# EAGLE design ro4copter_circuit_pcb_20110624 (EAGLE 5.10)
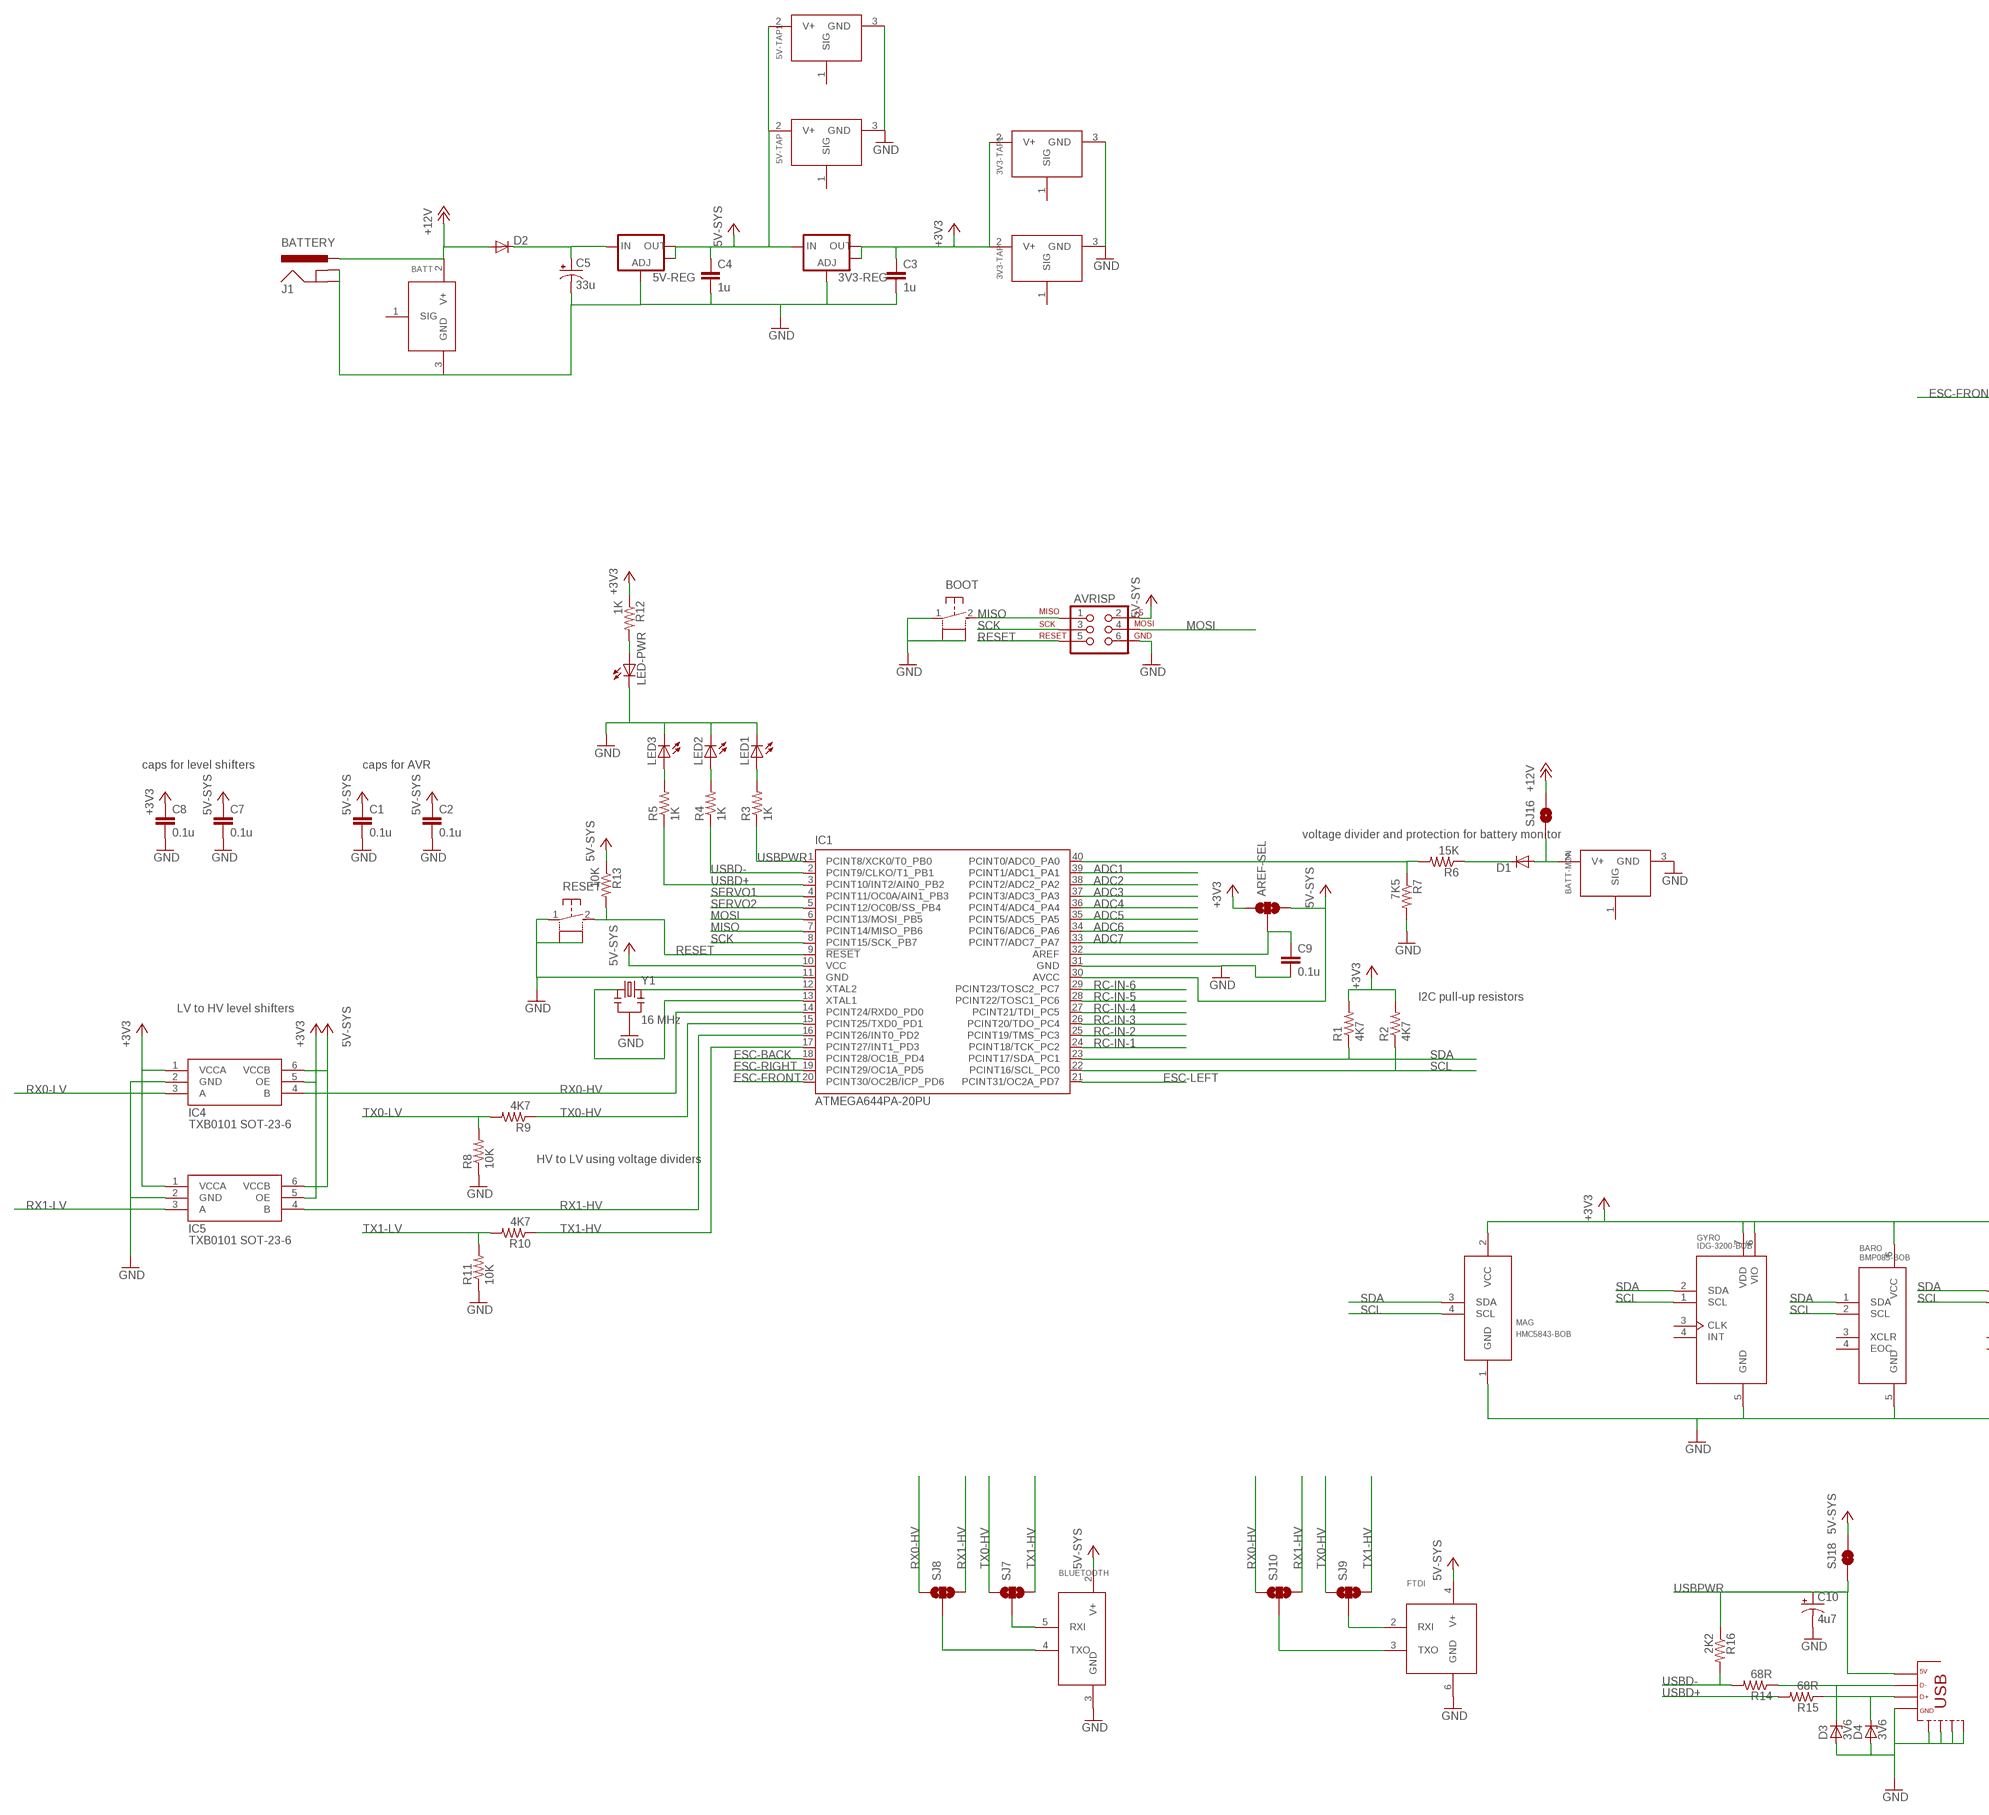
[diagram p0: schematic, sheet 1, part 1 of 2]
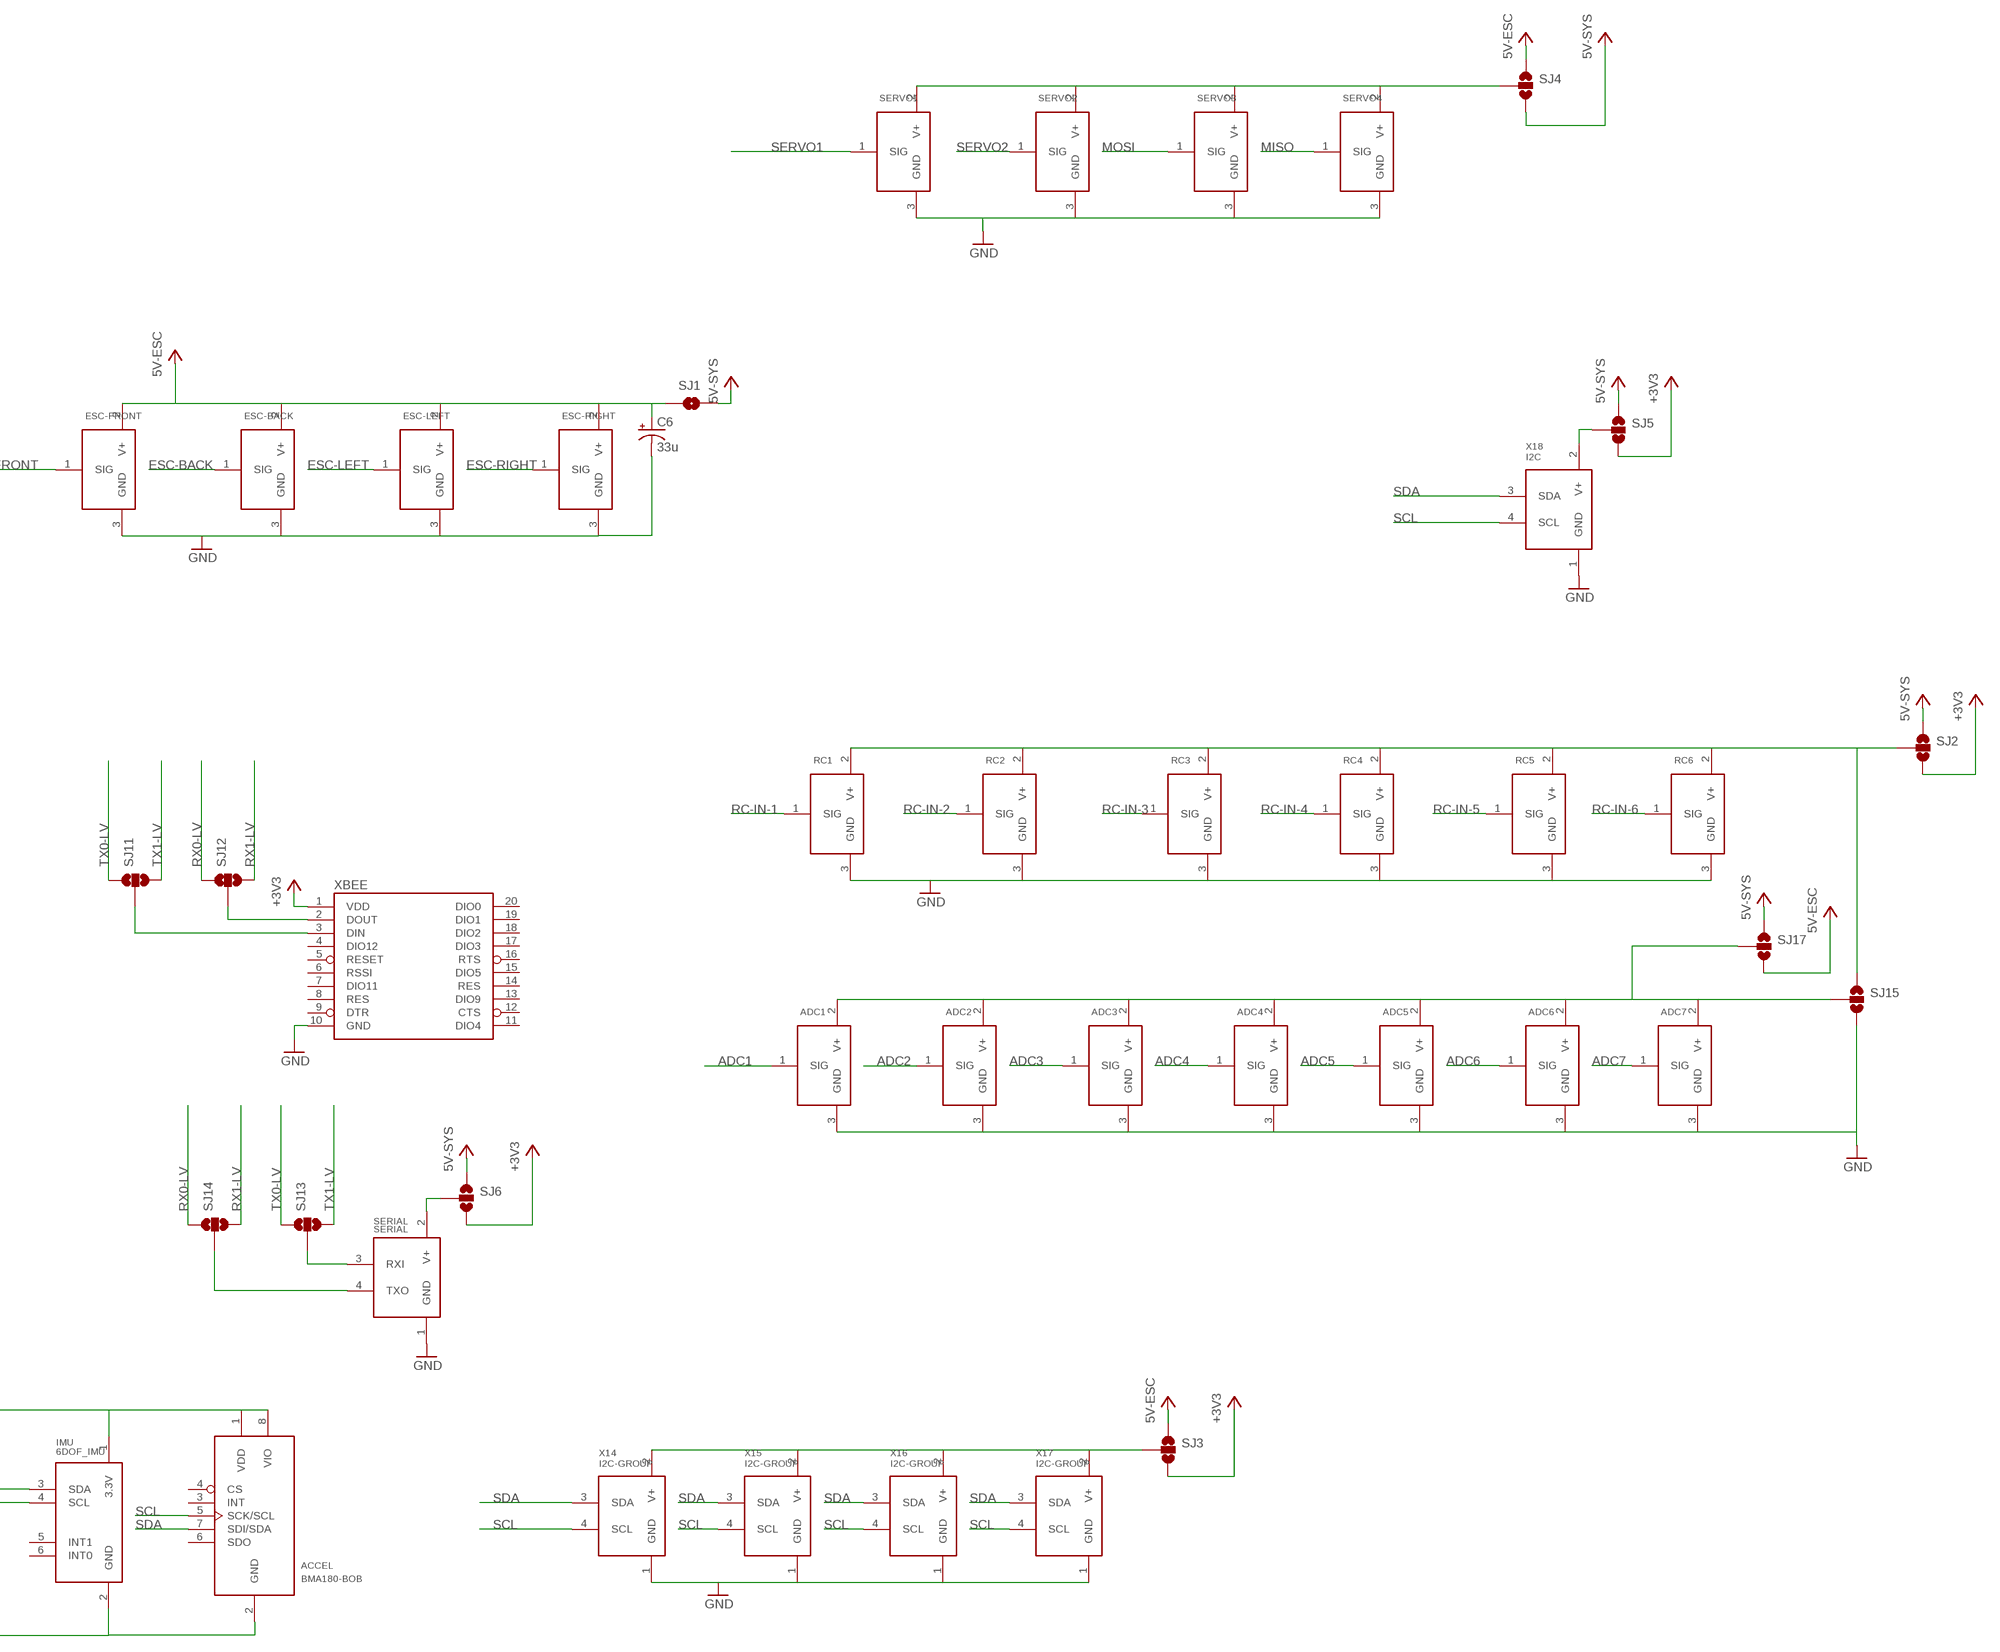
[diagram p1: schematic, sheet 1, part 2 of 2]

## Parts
3V3-REG  V_REG_LM1117SOT223  [SOT223]
3V3-TAP  SERVO-3PINSTANDARD  [SERVO-3PIN]
3V3-TAP1  SERVO-3PINSTANDARD  [SERVO-3PIN]
5V-REG  V_REG_LM1117SOT223  [SOT223]
5V-TAP  SERVO-3PINSTANDARD  [SERVO-3PIN]
5V-TAP1  SERVO-3PINSTANDARD  [SERVO-3PIN]
ACCEL  BMA180-BOB  [BMA180-BOB]
ADC1  SERVO-3PINSTANDARD  [SERVO-3PIN]
ADC2  SERVO-3PINSTANDARD  [SERVO-3PIN]
ADC3  SERVO-3PINSTANDARD  [SERVO-3PIN]
ADC4  SERVO-3PINSTANDARD  [SERVO-3PIN]
ADC5  SERVO-3PINSTANDARD  [SERVO-3PIN]
ADC6  SERVO-3PINSTANDARD  [SERVO-3PIN]
ADC7  SERVO-3PINSTANDARD  [SERVO-3PIN]
AREF-SEL  SOLDERJUMPER_2WAYFERRITE-BEAD  [SJ-FERRITE-BEAD]
AVRISP  AVR_SPI_PRG_6NS  [2X3-NS]
BARO  BMP085-BOB  [BMP085-BOB]
BATT  SERVO-3PINSTANDARD  [SERVO-3PIN]
BATT-MON  SERVO-3PINSTANDARD  [SERVO-3PIN]
BLUETOOTH  BLUESMIRF-CONN  [BLUESMIRF-CONN]
BOOT  SWITCH-TACT-SIDE-31-XX  [B3F-31XX]
C1  0.1u  C-EUC0805  [C0805]
C2  0.1u  C-EUC0805  [C0805]
C3  1u  C-EUC0805  [C0805]
C4  1u  C-EUC0805  [C0805]
C5  33u  CPOL-US153CLV-0505  [153CLV-0505]
C6  33u  CPOL-US153CLV-0505  [153CLV-0505]
C7  0.1u  C-EUC0805  [C0805]
C8  0.1u  C-EUC0805  [C0805]
C9  0.1u  C-EUC0805  [C0805]
C10  4u7  CPOL-USB/3528-21W  [B/3528-21W]
D1  DIODE-MINIMELF  [MINIMELF]
D2  DIODE-SMB  [SMB]
D3  3V6  ZENER-DIODESOD80C  [SOD80C]
D4  3V6  ZENER-DIODESOD80C  [SOD80C]
ESC-BACK  SERVO-3PINSTANDARD  [SERVO-3PIN]
ESC-FRONT  SERVO-3PINSTANDARD  [SERVO-3PIN]
ESC-LEFT  SERVO-3PINSTANDARD  [SERVO-3PIN]
ESC-RIGHT  SERVO-3PINSTANDARD  [SERVO-3PIN]
FTDI  FTDI-CABLE  [FTDI-CABLE-EDGE]
GYRO  IDG-3200-BOB  [ITG-3200-BOB]
IC1  ATMEGA644PA-20PU  ATMEGA644-20PU  [DIL40]
IC4  TXB0101 SOT-23-6  TXB0101SOT-23-6  [SOT-23-6]
IC5  TXB0101 SOT-23-6  TXB0101SOT-23-6  [SOT-23-6]
IMU  6DOF_IMU  [6DOF_IMU]
J1  BATTERY  POWER_JACKPTH  [POWER_JACK_PTH]
LED1  LED3MM  [LED3MM]
LED2  LED3MM  [LED3MM]
LED3  LED3MM  [LED3MM]
LED-PWR  LED3MM  [LED3MM]
MAG  HMC5843-BOB  [HMC5843-BOB]
R1  4K7  R-US_R0805  [R0805]
R2  4K7  R-US_R0805  [R0805]
R3  1K  R-US_R0805  [R0805]
R4  1K  R-US_R0805  [R0805]
R5  1K  R-US_R0805  [R0805]
R6  15K  R-US_R0805  [R0805]
R7  7K5  R-US_R0805  [R0805]
R8  10K  R-US_R0805  [R0805]
R9  4K7  R-US_R0805  [R0805]
R10  4K7  R-US_R0805  [R0805]
R11  10K  R-US_R0805  [R0805]
R12  1K  R-US_R0805  [R0805]
R13  10K  R-US_R0805  [R0805]
R14  68R  R-US_R0805  [R0805]
R15  68R  R-US_R0805  [R0805]
R16  2K2  R-US_R0805  [R0805]
RC1  SERVO-3PINSTANDARD  [SERVO-3PIN]
RC2  SERVO-3PINSTANDARD  [SERVO-3PIN]
RC3  SERVO-3PINSTANDARD  [SERVO-3PIN]
RC4  SERVO-3PINSTANDARD  [SERVO-3PIN]
RC5  SERVO-3PINSTANDARD  [SERVO-3PIN]
RC6  SERVO-3PINSTANDARD  [SERVO-3PIN]
RESET  SWITCH-TACT-SIDE-31-XX  [B3F-31XX]
SERIAL  SERIAL  SERIAL-CONN  [SERIAL-CONN]
SERVO1  SERVO-3PINSTANDARD  [SERVO-3PIN]
SERVO2  SERVO-3PINSTANDARD  [SERVO-3PIN]
SERVO3  SERVO-3PINSTANDARD  [SERVO-3PIN]
SERVO4  SERVO-3PINSTANDARD  [SERVO-3PIN]
SJ1  SOLDERJUMPERNO  [SJ_2S-NO]
SJ2  SOLDERJUMPER_2WAYT  [SJ_2]
SJ3  SOLDERJUMPER_2WAYT  [SJ_2]
SJ4  SOLDERJUMPER_2WAYT  [SJ_2]
SJ5  SOLDERJUMPER_2WAYT  [SJ_2]
SJ6  SOLDERJUMPER_2WAYT  [SJ_2]
SJ7  SOLDERJUMPER_2WAYT  [SJ_2]
SJ8  SOLDERJUMPER_2WAYT  [SJ_2]
SJ9  SOLDERJUMPER_2WAYT  [SJ_2]
SJ10  SOLDERJUMPER_2WAYT  [SJ_2]
SJ11  SOLDERJUMPER_2WAYT  [SJ_2]
SJ12  SOLDERJUMPER_2WAYT  [SJ_2]
SJ13  SOLDERJUMPER_2WAYT  [SJ_2]
SJ14  SOLDERJUMPER_2WAYT  [SJ_2]
SJ15  SOLDERJUMPER_2WAYT  [SJ_2]
SJ16  SOLDERJUMPERNO  [SJ_2S-NO]
SJ17  SOLDERJUMPER_2WAYT  [SJ_2]
SJ18  SOLDERJUMPERNO  [SJ_2S-NO]
U$5  USB-MINIB-WSHIELD  [USB-MINIB]
X14  I2C-GROUP  [I2C-GROUP]
X15  I2C-GROUP  [I2C-GROUP]
X16  I2C-GROUP  [I2C-GROUP]
X17  I2C-GROUP  [I2C-GROUP]
X18  I2C  I2C-GROUP  [I2C-GROUP]
XBEE  XBEE-1XBEE-1_LOCK  [XBEE-1_LOCK]
Y1  16 MHz  RESONATORPTH  [RESONATOR-PTH]

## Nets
5V-ESC: C6.+ ESC-BACK.2(V+) ESC-FRONT.2(V+) ESC-LEFT.2(V+) ESC-RIGHT.2(V+) SJ1.1 SJ3.1 SJ4.1 SJ17.3
+3V3: 3V3-REG.2(OUT) 3V3-REG.4(OUT) 3V3-TAP1.2(V+) 3V3-TAP.2(V+) ACCEL.1(VDD) ACCEL.8(VIO) AREF-SEL.1 BARO.6(VCC) C3.1 C8.1 GYRO.6(VIO) GYRO.7(VDD) IC4.1(VCCA) IC4.5(OE) IC5.1(VCCA) IC5.5(OE) IMU.1(3.3V) MAG.2(VCC) R1.2 R2.2 R12.1 SJ2.3 SJ3.3 SJ5.3 SJ6.3 XBEE.1(VDD)
+5V: 3V3-REG.3(IN) 5V-REG.2(OUT) 5V-REG.4(OUT) 5V-TAP1.2(V+) 5V-TAP.2(V+) AREF-SEL.3 AVRISP.2 BLUETOOTH.2(V+) C1.1 C2.1 C4.1 C7.1 FTDI.4(V+) IC1.10(VCC) IC1.30(AVCC) IC4.6(VCCB) IC5.6(VCCB) R13.1 SJ1.2 SJ2.1 SJ4.3 SJ5.1 SJ6.1 SJ17.1 SJ18.2 ; supply symbol labelled 5V-SYS
+12V: BATT.2(V+) D2.A J1.PWR SJ16.2
ADC1: ADC1.1(SIG) IC1.39(PCINT1/ADC1_PA1)
ADC2: ADC2.1(SIG) IC1.38(PCINT2/ADC2_PA2)
ADC3: ADC3.1(SIG) IC1.37(PCINT3/ADC3_PA3)
ADC4: ADC4.1(SIG) IC1.36(PCINT4/ADC4_PA4)
ADC5: ADC5.1(SIG) IC1.35(PCINT5/ADC5_PA5)
ADC6: ADC6.1(SIG) IC1.34(PCINT6/ADC6_PA6)
ADC7: ADC7.1(SIG) IC1.33(PCINT7/ADC7_PA7)
ESC-BACK: ESC-BACK.1(SIG) IC1.18(PCINT28/OC1B_PD4)
ESC-FRONT: ESC-FRONT.1(SIG) IC1.20(PCINT30/OC2B/ICP_PD6)
ESC-LEFT: ESC-LEFT.1(SIG) IC1.21(PCINT31/OC2A_PD7)
ESC-RIGHT: ESC-RIGHT.1(SIG) IC1.19(PCINT29/OC1A_PD5)
GND: 3V3-REG.1(ADJ) 3V3-TAP1.3(GND) 3V3-TAP.3(GND) 5V-REG.1(ADJ) 5V-TAP1.3(GND) 5V-TAP.3(GND) ACCEL.2(GND) ADC1.3(GND) ADC2.3(GND) ADC3.3(GND) ADC4.3(GND) ADC5.3(GND) ADC6.3(GND) ADC7.3(GND) AVRISP.6 BARO.5(GND) BATT-MON.3(GND) BATT.3(GND) BLUETOOTH.3(GND) BOOT.1(P) BOOT.S@3(S) BOOT.S@4(S) C1.2 C2.2 C3.2 C4.2 C5.- C6.- C7.2 C8.2 C9.2 C10.- D3.A D4.A ESC-BACK.3(GND) ESC-FRONT.3(GND) ESC-LEFT.3(GND) ESC-RIGHT.3(GND) FTDI.6(GND) GYRO.5(GND) IC1.11(GND) IC1.31(GND) IC4.2(GND) IC5.2(GND) IMU.2(GND) J1.GND J1.GNDBREAK LED1.K(C) LED2.K(C) LED3.K(C) LED-PWR.K(C) MAG.1(GND) R7.2 R8.1 R11.1 RC1.3(GND) RC2.3(GND) RC3.3(GND) RC4.3(GND) RC5.3(GND) RC6.3(GND) RESET.1(P) RESET.S@3(S) RESET.S@4(S) SERIAL.1(GND) SERVO1.3(GND) SERVO2.3(GND) SERVO3.3(GND) SERVO4.3(GND) SJ15.3 U$5.GND U$5.GND@1(SHIELD) U$5.GND@2(SHIELD) U$5.GND@3(SHIELD) U$5.GND@4(SHIELD) X14.1(GND) X15.1(GND) X16.1(GND) X17.1(GND) X18.1(GND) XBEE.10(GND) Y1.2
MISO: AVRISP.1 BOOT.2(S) IC1.7(PCINT14/MISO_PB6) SERVO4.1(SIG)
MOSI: AVRISP.4 IC1.6(PCINT13/MOSI_PB5) SERVO3.1(SIG)
N$1: IC1.12(XTAL2) Y1.3
N$2: IC1.13(XTAL1) Y1.1
N$3: LED3.A R5.2
N$4: LED2.A R4.2
N$5: LED1.A R3.2
N$6: SJ3.2 X14.2(V+) X15.2(V+) X16.2(V+) X17.2(V+)
N$8: RC1.2(V+) RC2.2(V+) RC3.2(V+) RC4.2(V+) RC5.2(V+) RC6.2(V+) SJ2.2 SJ15.1
N$11: IC1.40(PCINT0/ADC0_PA0) R6.2 R7.1
N$12: SJ5.2 X18.2(V+)
N$13: D1.C R6.1
N$14: BATT-MON.2(V+) D1.A SJ16.1
N$15: SERIAL.2(V+) SJ6.2
N$16: 5V-REG.3(IN) C5.+ D2.C
N$17: BLUETOOTH.5(RXI) SJ7.2
N$18: BLUETOOTH.4(TXO) SJ8.2
N$19: FTDI.2(RXI) SJ9.2
N$20: SERVO1.2(V+) SERVO2.2(V+) SERVO3.2(V+) SERVO4.2(V+) SJ4.2
N$21: FTDI.3(TXO) SJ10.2
N$22: SJ12.2 XBEE.2(DOUT)
N$23: SJ11.2 XBEE.3(DIN)
N$24: LED-PWR.A R12.2
N$25: AREF-SEL.2 C9.1 IC1.32(AREF)
N$31: SERIAL.3(RXI) SJ13.2
N$32: SERIAL.4(TXO) SJ14.2
N$34: ADC1.2(V+) ADC2.2(V+) ADC3.2(V+) ADC4.2(V+) ADC5.2(V+) ADC6.2(V+) ADC7.2(V+) SJ15.2 SJ17.2
N$42: D3.C R14.1 U$5.D-
N$43: D4.C R15.1 U$5.D+
RC-IN-1: IC1.24(PCINT18/TCK_PC2) RC1.1(SIG)
RC-IN-2: IC1.25(PCINT19/TMS_PC3) RC2.1(SIG)
RC-IN-3: IC1.26(PCINT20/TDO_PC4) RC3.1(SIG)
RC-IN-4: IC1.27(PCINT21/TDI_PC5) RC4.1(SIG)
RC-IN-5: IC1.28(PCINT22/TOSC1_PC6) RC5.1(SIG)
RC-IN-6: IC1.29(PCINT23/TOSC2_PC7) RC6.1(SIG)
RESET: AVRISP.5 IC1.9(!RESET) R13.2 RESET.2(S)
RX0-HV: IC1.14(PCINT24/RXD0_PD0) IC4.4(B) SJ8.1 SJ10.1
RX0-LV: IC4.3(A) SJ12.1 SJ14.1
RX1-HV: IC1.16(PCINT26/INT0_PD2) IC5.4(B) SJ8.3 SJ10.3
RX1-LV: IC5.3(A) SJ12.3 SJ14.3
SCK: AVRISP.3 IC1.8(PCINT15/SCK_PB7)
SCL: ACCEL.5(SCK/SCL) BARO.2(SCL) GYRO.1(SCL) IC1.22(PCINT16/SCL_PC0) IMU.4(SCL) MAG.4(SCL) R2.1 X14.4(SCL) X15.4(SCL) X16.4(SCL) X17.4(SCL) X18.4(SCL)
SDA: ACCEL.7(SDI/SDA) BARO.1(SDA) GYRO.2(SDA) IC1.23(PCINT17/SDA_PC1) IMU.3(SDA) MAG.3(SDA) R1.1 X14.3(SDA) X15.3(SDA) X16.3(SDA) X17.3(SDA) X18.3(SDA)
SERVO1: IC1.4(PCINT11/OC0A/AIN1_PB3) SERVO1.1(SIG)
SERVO2: IC1.5(PCINT12/OC0B/SS_PB4) SERVO2.1(SIG)
TX0-HV: IC1.15(PCINT25/TXD0_PD1) R9.1 SJ7.1 SJ9.1
TX0-LV: R8.2 R9.2 SJ11.1 SJ13.1
TX1-HV: IC1.17(PCINT27/INT1_PD3) R10.1 SJ7.3 SJ9.3
TX1-LV: R10.2 R11.2 SJ11.3 SJ13.3
USBD+: IC1.3(PCINT10/INT2/AIN0_PB2) R5.1 R15.2
USBD-: IC1.2(PCINT9/CLKO/T1_PB1) R4.1 R14.2 R16.2
USBPWR: C10.+ IC1.1(PCINT8/XCK0/T0_PB0) R3.1 R16.1 SJ18.1 U$5.VBUS(V+)
Unconnected: 3V3-TAP1.1(SIG) 3V3-TAP.1(SIG) 5V-TAP1.1(SIG) 5V-TAP.1(SIG) ACCEL.3(INT) ACCEL.4(CS) ACCEL.6(SDO) BARO.3(XCLR) BARO.4(EOC) BATT-MON.1(SIG) BATT.1(SIG) GYRO.3(CLK) GYRO.4(INT) IMU.5(INT1) IMU.6(INT0) XBEE.4(DIO12) XBEE.5(RESET) XBEE.6(RSSI) XBEE.7(DIO11) XBEE.8(RES) XBEE.9(DTR) XBEE.11(DIO4) XBEE.12(CTS) XBEE.13(DIO9) XBEE.14(RES) XBEE.15(DIO5) XBEE.16(RTS) XBEE.17(DIO3) XBEE.18(DIO2) XBEE.19(DIO1) XBEE.20(DIO0)

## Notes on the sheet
- caps for level shifters | caps for AVR
- voltage divider and protection for battery monitor
- I2C pull-up resistors
- LV to HV level shifters
- HV to LV using voltage dividers

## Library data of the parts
3V3-REG 5V-REG = aq_pcb_v2:V_REG_LM1117: Voltage Regulator LM1117 Standard adjustable voltage regulator but in SMD form. Spark Fun Electronics SKU : COM-00595
3V3-TAP 3V3-TAP1 5V-TAP 5V-TAP1 ADC1-ADC7 BATT BATT-MON ESC-BACK ESC-FRONT ESC-LEFT ESC-RIGHT RC1-RC6 SERVO1-SERVO4 = aq_pcb_v2:SERVO-3PIN
ACCEL = aq_pcb_v2:BMA180-BOB
AREF-SEL SJ2-SJ15 SJ17 = aq_pcb_v2:SOLDERJUMPER_2WAY: Solder Jumper 2 way solder jumper
AVRISP = aq_pcb_v2:AVR_SPI_PRG_6: AVR ISP 6 Pin This is the reduced ISP connector for AVR programming. Common on Arduino. This footprint will take up less PCB space and can be used with a 10-pin to 6-pin adapter such as SKU: BOB-08508
BARO = aq_pcb_v2:BMP085-BOB
BLUETOOTH = aq_pcb_v2:BLUESMIRF-CONN
BOOT RESET = aq_pcb_v2:SWITCH-TACT-SIDE-31-XX: OMRON SWITCH
C1-C4 C7-C9 = rcl:C-EU: CAPACITOR, European symbol
C5 C6 C10 = rcl:CPOL-US: POLARIZED CAPACITOR, American symbol
D1 D2 = diode:DIODE-: DIODE
D3 D4 = diode:ZENER-DIODE: Z-Diode
FTDI = aq_pcb_v2:FTDI-CABLE
GYRO = aq_pcb_v2:IDG-3200-BOB
IC1 = aq_pcb_v2:ATMEGA644-*PU: 8-bit Microcontroller with 64K Bytes In-System Programmable Flash Auto generated by make-symbol-device-package-bsdl.ulp Rev. 34 Source: http://www.atmel.com/dyn/resources/prod_documents/doc2593.pdf
IC4 IC5 = aq_pcb_v2:TXB0101
IMU = aq_pcb_v2:6DOF_IMU
J1 = aq_pcb_v2:POWER_JACK: Power Jack This is the standard 5.5mm barrel jack for power. The PTH is the most common, proven, reliable, footprint. All others are experimental. The Slot footprint only works if the mill layer is transmitted to the PCB fab house so be warned. Spark Fun Electronics SKU : PRT-00119. Mating wall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
LED1-LED3 LED-PWR = aq_pcb_v2:LED: LEDs
MAG = aq_pcb_v2:HMC5843-BOB
R1-R16 = rcl:R-US_: RESISTOR, American symbol
SERIAL = aq_pcb_v2:SERIAL-CONN
SJ1 SJ16 SJ18 = aq_pcb_v2:SOLDERJUMPER: Solder Jumper
U$5 = aq_pcb_v2:USB-MINIB-WSHIELD
X14-X18 = aq_pcb_v2:I2C-GROUP
XBEE = aq_pcb_v2:XBEE-1
Y1 = aq_pcb_v2:RESONATOR: Resonator Small SMD resonator. This is the itty bitty 10/20MHz resonators with built in caps. CSTCE10M0G55 and CSTCE20M0V53. Footprint has been reviewed closely but hasn't been tested yet.

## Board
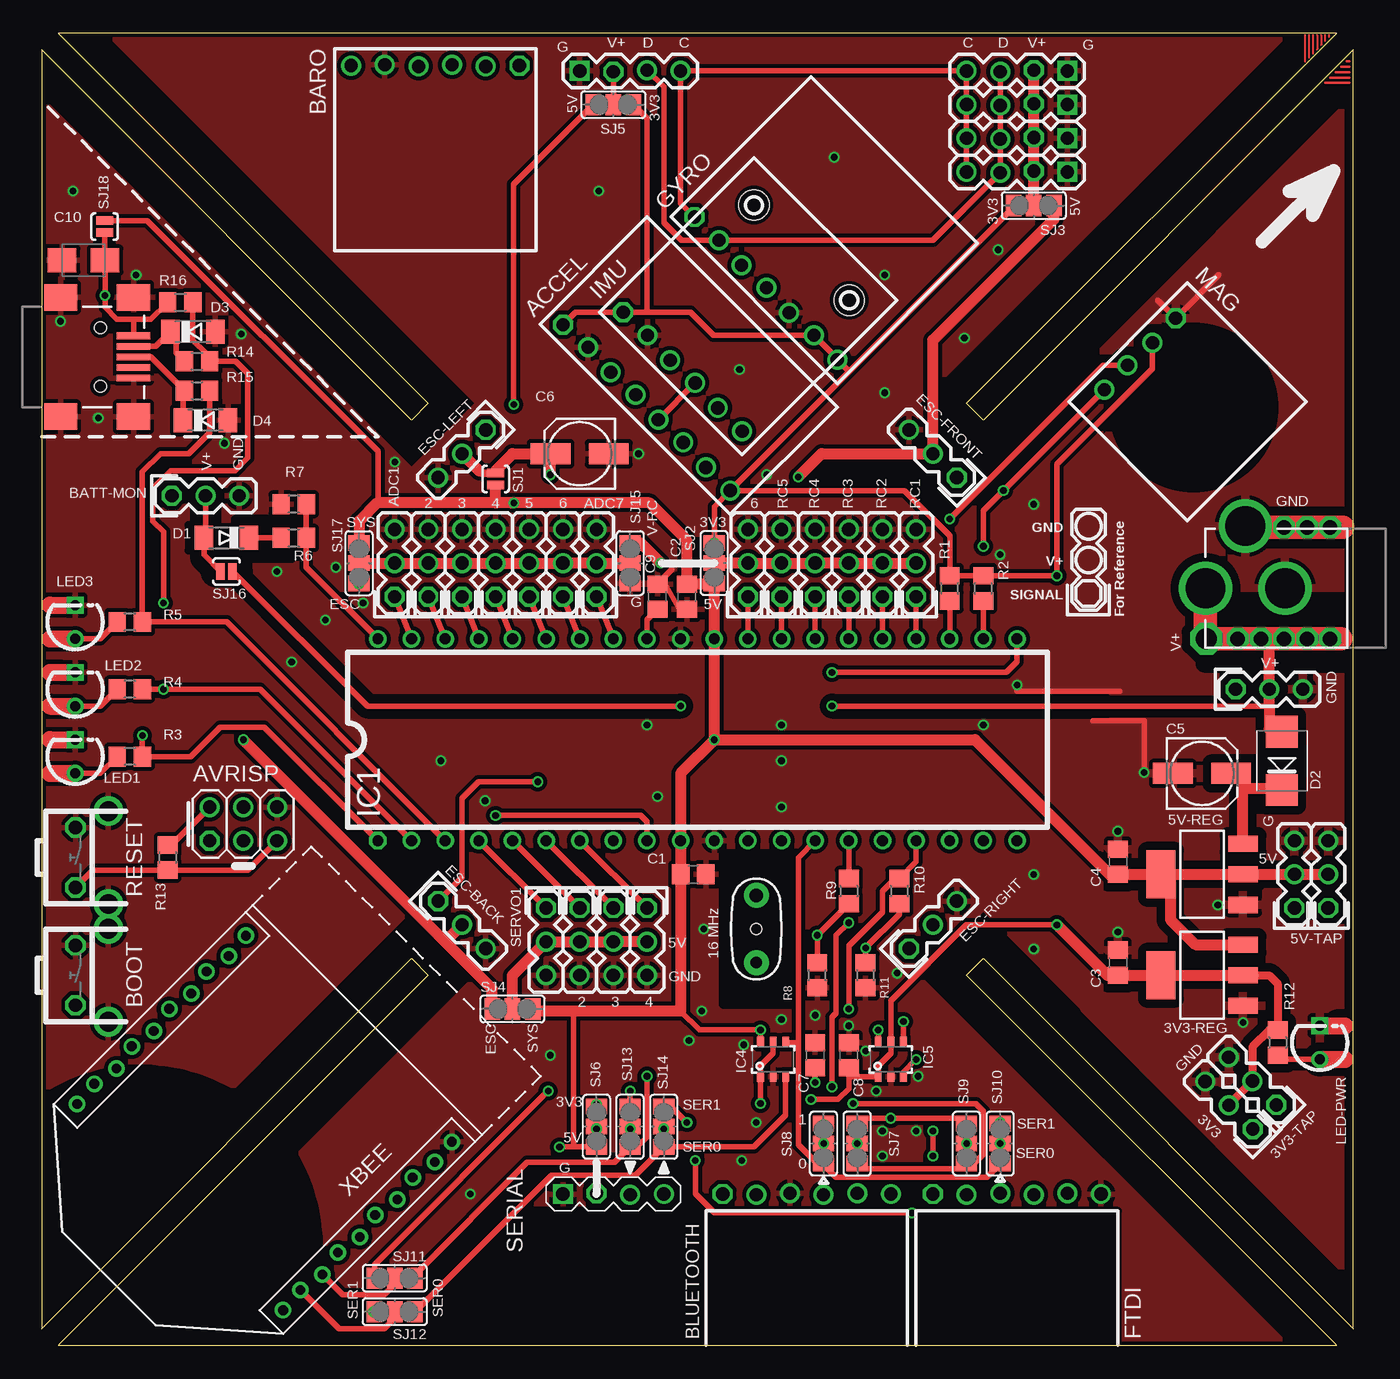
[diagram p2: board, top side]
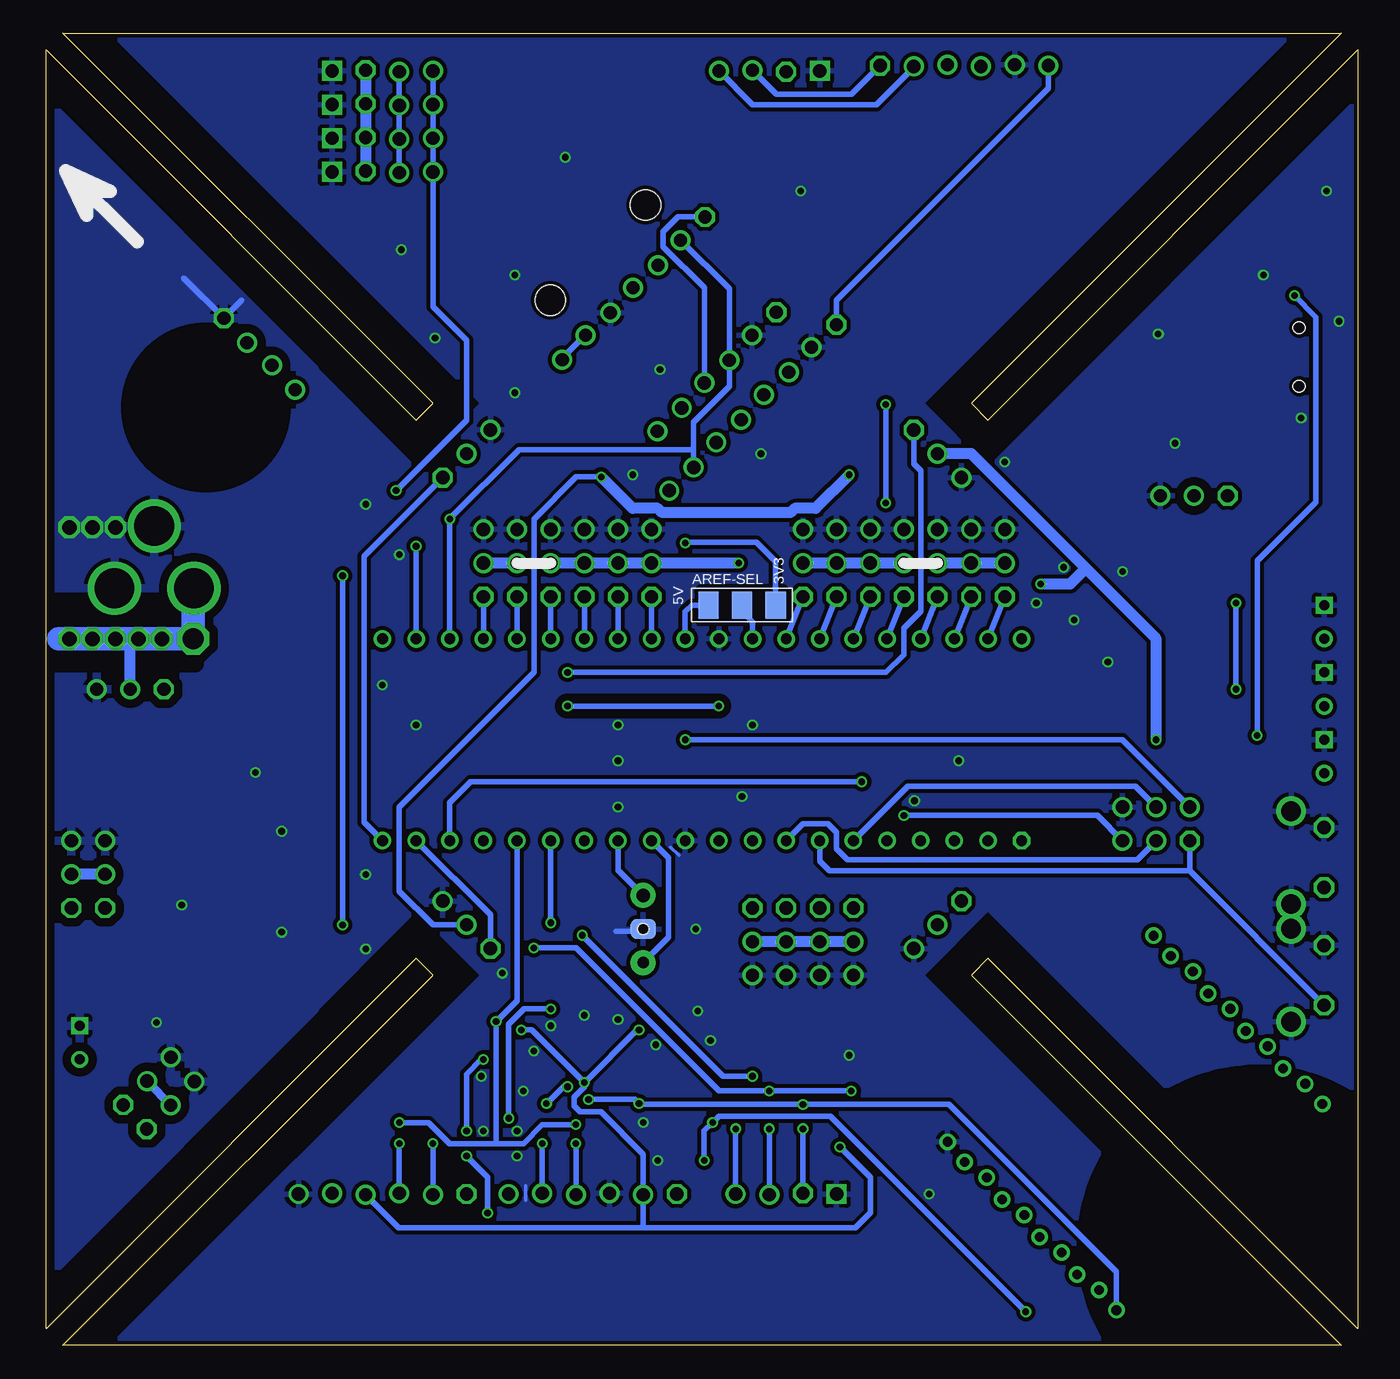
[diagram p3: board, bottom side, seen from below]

Size 99.06 x 99.06 mm. Coordinates in mm from the lower left corner, seen from the top.
Outline: 27.94,29.21 29.21,27.94 1.27,0 97.79,0 69.85,27.94 71.12,29.21 99.06,1.27 99.06,97.79 71.12,69.85 69.85,71.12 97.79,99.06 1.27,99.06 29.21,71.12 27.94,69.85 0,97.79 0,1.27 27.94,29.21
Copper layers (1*16): Top 0.035mm / dielectric 1.5mm / Bottom 0.035mm
Design rules "Fusion_eagle_rule_v1.1_TentedVias2 *": minimum track width 6mil, minimum drill 0.5mm, track to track 6mil, track to pad 6mil, pad to pad 6mil, via to via 6mil, smd to smd 0mil, copper to edge 10mil, drill to drill 10mil, minimum pad ring 10mil, minimum via ring 6mil, stop-mask expansion 2mil, vias tented up to drill 25mil, thermal gap 12mil
tKeepout: area 36.8,0 to 49.5,10.2
tRestrict: area 36.8,0 to 49.5,10.2; area 92.4,43.2 to 94.9,45.1; area 13,60.2 to 14.9,61.8; area 87.8,51.4 to 99.1,56.2; area 12.2,63.9 to 12.6,64.4; area 14.6,59.4 to 18.9,62.4; area 11.1,60 to 11.7,61.9; 13 lines
bRestrict: area 87.8,51.4 to 99.1,56.2; area 12.2,63.9 to 12.6,64.4; 1 lines

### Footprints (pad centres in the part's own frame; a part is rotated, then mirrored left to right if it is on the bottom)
SOT223 = smd 1.219 x 2.235: 1 -2.311,-3.099; 2 0,-3.099; 3 2.311,-3.099 | smd 3.6 x 2.2: 4 0,3.099
SERVO-3PIN = drill 1 octagon: 1 0,-2.54 | drill 1 round: 2 0,0; 3 0,2.54
BMA180-BOB = drill 1 octagon: 1 -8.89,-0.064 | drill 1 round: 2 -6.35,0.064; 3 -3.81,-0.064; 4 -1.27,0.064; 5 1.27,-0.064; 6 3.81,0.064; 7 6.35,-0.064; 8 8.89,0
SJ-FERRITE-BEAD = smd 1.524 x 2.032: 1 -2.54,0; 2 0,0; 3 2.54,0
2X3-NS = drill 1 octagon: 1 -2.54,-1.27 | drill 1 round: 2 -2.54,1.27; 3 0,-1.27; 4 0,1.27; 5 2.54,-1.27; 6 2.54,1.27
BMP085-BOB = drill 1 octagon: 1 -6.35,0 | drill 1 round: 2 -3.81,0.064; 3 -1.27,-0.064; 4 1.27,0.064; 5 3.81,-0.064; 6 6.35,0
BLUESMIRF-CONN = drill 1 octagon: 1 -6.35,0 | drill 1 round: 2 -3.81,-0.064; 3 -1.27,0.064; 4 1.27,-0.064; 5 3.81,0.064; 6 6.35,0
B3F-31XX = drill 1.016 octagon: 1 -2.261,-1.245; 2 2.261,-1.245 | drill 1.499 pad 2.159 round: S@3 -3.505,1.245; S@4 3.505,1.245
C0805 = smd 1.3 x 1.5: 1 -0.95,0; 2 0.95,0
153CLV-0505 = smd 3 x 1.6: + 2.2,0; - -2.2,0
B/3528-21W = smd 2.15 x 1.8: + 1.625,0; - -1.625,0
MINIMELF = smd 1.4 x 1.8: A 1.7,0; C -1.7,0
SMB = smd 2.4 x 2.4: A 2.2,0; C -2.2,0
SOD80C = smd 1.4 x 1.8: A 1.7,0; C -1.7,0
FTDI-CABLE-EDGE = drill 1 octagon: 1 -6.35,0 | drill 1 round: 2 -3.81,-0.064; 3 -1.27,0.064; 4 1.27,-0.064; 5 3.81,0.064; 6 6.35,0
ITG-3200-BOB = drill 1 octagon: 1 -7.62,0 | drill 1 round: 2 -5.08,0.064; 3 -2.54,-0.064; 4 0,0.064; 5 2.54,-0.064; 6 5.08,0.064; 7 7.62,0
DIL40 = drill 0.813 octagon: 1 -24.13,-7.62 | drill 0.813 round: 2 -21.59,-7.62; 3 -19.05,-7.62; 4 -16.51,-7.62; 5 -13.97,-7.62; 6 -11.43,-7.62; 7 -8.89,-7.62; 8 -6.35,-7.62; 9 -3.81,-7.62; 10 -1.27,-7.62; 11 1.27,-7.62; 12 3.81,-7.62; 13 6.35,-7.62; 14 8.89,-7.62; 15 11.43,-7.62; 16 13.97,-7.62; 17 16.51,-7.62; 18 19.05,-7.62; 19 21.59,-7.62; 20 24.13,-7.62; 21 24.13,7.62; 22 21.59,7.62; 23 19.05,7.62; 24 16.51,7.62; 25 13.97,7.62; 26 11.43,7.62; 27 8.89,7.62; 28 6.35,7.62; 29 3.81,7.62; 30 1.27,7.62; 31 -1.27,7.62; 32 -3.81,7.62; 33 -6.35,7.62; 34 -8.89,7.62; 35 -11.43,7.62; 36 -13.97,7.62; 37 -16.51,7.62; 38 -19.05,7.62; 39 -21.59,7.62; 40 -24.13,7.62
SOT-23-6 = smd 0.51 x 0.8: 1 -0.95,-1.3; 2 0,-1.3; 3 0.95,-1.3; 4 0.95,1.3; 5 0,1.3; 6 -0.95,1.3
6DOF_IMU = drill 1 octagon: 1 0,-6.35 | drill 1 round: 2 -0.064,-3.81; 3 0.064,-1.27; 4 -0.064,1.27; 5 0.064,3.81; 6 0,6.35 | hole 2.286: -12.7,5.08; -12.7,-5.08
POWER_JACK_PTH = drill 2.997 round: GND 0,7.7; GNDBREAK 4.7,10.7; PWR 0,13.7
LED3MM = drill 0.762 pad 1.27 round: A -1.27,0 | drill 0.762 pad 1.27 square: K 1.27,0
HMC5843-BOB = drill 1 octagon: 1 -3.81,0 | drill 1 round: 2 -1.27,0.064; 3 1.27,-0.064; 4 3.81,0
R0805 = smd 1.3 x 1.5: 1 -0.95,0; 2 0.95,0
SERIAL-CONN = drill 1 square: 1 -3.81,0 | drill 1 octagon: 2 -1.27,0.064 | drill 1 round: 3 1.27,-0.064; 4 3.81,0
SJ_2S-NO = smd 0.635 x 1.27: 1 -0.45,0; 2 0.45,0
SJ_2 = smd 1.168 x 1.6: 1 -1.524,0; 2 0,0; 3 1.524,0
USB-MINIB = smd 2.5 x 0.5: D+ 2.5,0; D- 2.5,0.8; GND 2.5,-1.6; ID 2.5,-0.8; VBUS 2.5,1.6 | smd 2.5 x 2: GND@1 -3,-4.5; GND@2 -3,4.5; GND@3 2.5,4.5; GND@4 2.5,-4.5 | hole 0.9: 0,2.2; 0,-2.2
I2C-GROUP = drill 1 square: 1 -3.81,0 | drill 1 octagon: 2 -1.27,-0.064 | drill 1 round: 3 1.27,0.064; 4 3.81,0
XBEE-1_LOCK = drill 0.737 round: 1 -10.987,20; 2 -10.822,18; 3 -11.178,16; 4 -10.822,14; 5 -11.178,12; 6 -10.822,10; 7 -11.178,8; 8 -10.822,6; 9 -11.178,4; 10 -11.013,2; 11 10.987,2; 12 10.822,4; 13 11.178,6; 14 10.822,8; 15 11.178,10; 16 10.822,12; 17 11.178,14; 18 10.822,16; 19 11.178,18; 20 11.013,20
RESONATOR-PTH = drill 1.016 pad 1.88 round: 1 -2.54,0 | smd 1.524 x 1.905 bottom: 2 0,0 | drill 0.864 pad 1.88 round: 3 2.54,0 | hole 0.825: 0,0

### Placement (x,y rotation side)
3V3-REG  87.63,27.94 90 top
3V3-TAP  91.44,19.95 45 top
3V3-TAP1  89.66,18.13 45 top
5V-REG  87.63,35.56 90 top
5V-TAP  94.61,35.56 0 top
5V-TAP1  97.16,35.56 0 top
ACCEL  45.72,70.81 315 top
ADC1  26.67,59.05 0 top
ADC2  29.21,59.05 0 top
ADC3  31.75,59.05 0 top
ADC4  34.29,59.05 0 top
ADC5  36.83,59.05 0 top
ADC6  39.37,59.05 0 top
ADC7  41.91,59.05 0 top
AREF-SEL  46.51,55.88 180 bottom
AVRISP  15.24,39.37 0 top
BARO  29.74,96.61 180 top
BATT  92.71,49.53 270 top
BATT-MON  12.38,64.14 270 top
BLUETOOTH  57.78,11.43 0 top
BOOT  3.81,27.94 270 top
C1  49.21,35.56 0 top
C2  48.74,56.52 270 top
C3  81.28,28.89 90 top
C4  81.28,36.51 90 top
C5  87.63,43.18 0 top
C6  40.64,67.31 180 top
C7  58.42,21.91 90 top
C8  60.96,21.91 90 top
C9  46.51,56.52 90 top
C10  3.17,81.92 0 top
D1  13.97,60.96 180 top
D2  93.66,44.13 90 top
D3  11.43,76.52 0 top
D4  12.38,69.85 0 top
ESC-BACK  31.75,31.75 225 top
ESC-FRONT  67.31,67.31 45 top
ESC-LEFT  31.75,67.31 135 top
ESC-RIGHT  67.31,31.75 315 top
FTDI  73.66,11.43 0 top
GYRO  54.7,79.79 315 top
IC1  49.53,45.72 0 top
IC4  55.24,21.59 0 top
IC5  64.14,21.59 0 top
IMU  48.41,73.51 225 top
J1  101.6,57.15 90 top
LED1  2.54,44.45 90 top
LED2  2.54,49.53 90 top
LED3  2.54,54.61 90 top
LED-PWR  96.52,22.86 90 top
MAG  82.95,74.84 225 top
R1  68.58,57.15 90 top
R2  71.12,57.15 90 top
R3  6.67,44.45 180 top
R4  6.67,49.53 180 top
R5  6.67,54.61 180 top
R6  19.05,60.96 0 top
R7  19.05,63.5 180 top
R8  58.58,27.94 90 top
R9  60.96,34.29 270 top
R10  64.77,34.29 270 top
R11  62.23,27.94 90 top
R12  93.34,22.86 270 top
R13  9.53,36.83 270 top
R14  11.75,74.3 0 top
R15  11.75,72.07 0 top
R16  10.48,78.74 0 top
RC1  66.04,59.05 0 top
RC2  63.5,59.05 0 top
RC3  60.96,59.05 0 top
RC4  58.42,59.05 0 top
RC5  55.88,59.05 0 top
RC6  53.34,59.05 0 top
RESET  3.81,36.83 270 top
SERIAL  43.18,11.43 0 top
SERVO1  38.1,30.48 180 top
SERVO2  40.64,30.48 180 top
SERVO3  43.18,30.48 180 top
SERVO4  45.72,30.48 180 top
SJ1  34.29,65.41 270 top
SJ2  50.8,59.05 90 top
SJ3  74.93,86.04 180 top
SJ4  35.56,25.4 0 top
SJ5  43.18,93.66 0 top
SJ6  41.91,16.51 90 top
SJ7  61.59,15.24 90 top
SJ8  59.05,15.24 90 top
SJ9  69.85,15.24 90 top
SJ10  72.39,15.24 90 top
SJ11  26.67,5.08 180 top
SJ12  26.67,2.54 180 top
SJ13  44.45,16.51 90 top
SJ14  46.99,16.51 90 top
SJ15  44.45,59.05 270 top
SJ16  13.97,58.42 0 top
SJ17  23.97,59.05 270 top
SJ18  4.76,84.45 90 top
U$2  [SERVO-3PIN-REFERENCE]  79.06,59.29 90 top
U$3  [ARROR-DIR-REFERENCE]  93.98,85.09 315 top
U$4  [ARROR-DIR-REFERENCE]  93.98,85.09 45 bottom
U$5  4.45,74.61 0 top
X14  73.66,96.2 180 top
X15  73.66,93.66 180 top
X16  73.66,91.12 180 top
X17  73.66,88.58 180 top
X18  44.45,96.2 0 top
XBEE  24.62,24.57 135 top
Y1  53.98,31.43 270 top

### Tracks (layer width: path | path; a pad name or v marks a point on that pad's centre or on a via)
5V-ESC  (via drill 0.5)
  Top 0.406: C6.+ 38.42,67.29 | SJ1.1 34.29,66.04
  Top 0.61: 33.05,66.01 33.18,65.88 SJ1.1
  Top 0.813: ESC-LEFT.2 33.05,66.01 | SJ4.1 34.04,26.92 30.48,30.48 | SJ3.1 76.45,85.03 67.31,75.88 ESC-FRONT.2 58.9,67.31 v57.15,65.56 | 38.42,67.29 v38.42,65.72 | 30.48,30.48 v15.24,45.72 | 30.48,30.48 ESC-BACK.2 | C6.+ 35.56,67.31 34.29,66.04 | SJ17.3 | v23.97,57.47 SJ17.3
  Bottom 0.406: ESC-RIGHT.2 69.85,31.75 72.39,34.29 72.39,40.64 62.23,50.8 62.23,62.38 59.04,65.56 v57.15,65.56
  Bottom 0.813: v15.24,45.72 15.24,53.34 20.56,58.66 | 20.56,58.66 29.21,67.31 ESC-LEFT.2 | v38.42,65.72 40.96,63.18 42.55,63.18 42.86,62.87 52.55,62.87 52.86,63.18 54.77,63.18 v57.15,65.56 | v23.97,57.47 21.75,57.47 20.56,58.66
+3V3  (via drill 0.5)
  Top 0.406: R1.2 R2.2 v76.68,58.1 76.68,66.52 83.89,73.73 MAG.2 | ACCEL.8 50.8,63.32 SJ2.3 | 60.96,20.29 IC5.1 63.19,21.12 64.14,22.07 IC5.5 64.14,26.04 69.85,31.75 v76.68,31.75 | 60.96,20.29 C8.1 | IC4.5 55.24,22.07 54.29,21.11 IC4.1 v54.29,18.26 | v58.1,18.57 60.15,18.57 60.96,19.38 60.96,20.29 | ACCEL.1 40.33,78 IMU.1 45.72,78 | 45.72,78 49,78 50.76,76.25 GYRO.6 60.09,74.49 GYRO.7 60.92,73.57 61.05,73.57 | SJ5.3 45.72,92.65 45.72,78 | 68.74,58.1 68.58,58.26 R1.2 | ACCEL.8 65.17,64.53 68.58,61.12 R1.2 | SJ3.3 73.41,85.93 61.05,73.57 | ACCEL.8 61.05,73.57 | v41.91,18.19 SJ6.3
  Top 0.61: 3V3-REG.2 92.71,27.94 93.34,27.3 R12.1 92.71,23.81 91.44,22.54 3V3-TAP.2 89.66,18.18 3V3-TAP1.2
  Top 0.813: 3V3-REG.2 3V3-REG.4 C3.1 80.48,27.94 v76.68,31.75
  Bottom 0.406: XBEE.1 18.25,5.54 30.89,18.19 v41.91,18.19 54.23,18.19 v54.29,18.26 54.61,18.57 v58.1,18.57 | v76.68,31.75 v76.68,58.1 | SJ2.3 50.74,60.64 45.44,60.64 43.97,59.18 AREF-SEL.1 | BARO.6 23.39,94.88 39.39,78.88 ACCEL.1 | 60.48,74.14 58.42,76.2 58.38,76.25 GYRO.6
  Bottom 0.61: 3V3-TAP.2 91.44,19.92 89.61,18.1
  other vias: 50.8,60.58
+5V  (via drill 0.5)
  Top 0.406: v58.42,19.84 C7.1 | IC4.6 v54.29,23.81 49.69,23.81 48.26,25.24 | IC5.6 63.19,23.65 v63.18,23.81 | v39.12,14.99 SJ6.1 | 80.8,35.4 C4.1 | 37.15,25.24 37.15,25.34 SJ4.3 | 34.29,64.77 SJ1.2 | v35.65,71.03 35.65,87.66 SJ5.1 | 40.16,25.24 40.16,15.08 | AVRISP.2 10,37.94 R13.1 | 25.4,63.59 25.4,67.48 7.97,84.91 SJ18.2
  Top 0.813: C4.1 5V-REG.4 85.25,35.56 | 85.25,35.56 5V-REG.2 5V-TAP.2 5V-TAP1.2 | v50.8,45.72 48.26,43.18 IC1.10 C1.1 48.26,25.24 40.16,25.24 37.15,25.24 | v50.8,45.72 IC1.30 SJ2.1 50.8,57.47 C2.1 48.74,60.78 45.92,63.59 v35.65,63.59 | v50.8,45.72 70.48,45.72 80.8,35.4 | v35.65,63.59 35.47,63.59 | SJ17.1 | SJ17.1 23.97,62.23 25.33,63.59 25.4,63.59 34.29,63.59 | v35.65,63.59 34.29,63.59 | 34.29,63.59 34.29,64.77 | 3V3-REG.3 87.14,30.25 85.25,32.14 85.25,35.56
  Bottom 0.406: AVRISP.2 17.78,45.72 v50.8,45.72 | v39.12,14.99 36.83,12.7 36.83,10.01 37.95,8.89 53.98,8.89 | FTDI.4 72.45,8.89 53.98,8.89 | 53.98,8.89 BLUETOOTH.2 53.98,14.45 57.15,17.62 | v58.42,19.84 54.45,23.81 v54.29,23.81 | v63.18,23.81 62.39,23.81 v58.42,19.84 | v58.42,19.84 58.42,19.53 59.21,18.73 59.21,18.1 58.74,17.62 57.15,17.62 | 57.15,17.62 | v35.65,63.59 v35.65,71.03 | IC1.30 50.8,55.38 50.3,55.88 AREF-SEL.3
  Bottom 0.813: 5V-TAP.2 5V-TAP1.2
+12V  (via drill 0.5, 1.1, 1.6)
  Top 0.406: SJ16.2 14.45,58.42 24.61,48.26 v48.26,48.26 | v59.69,48.26 92.71,48.26
  Top 0.813: D2.A 92.71,46.51 92.71,48.26 BATT.2 92.71,53.34
  Top 1.778: J1.PWR 87.9,53.34 v90.33,53.34 | 98.11,53.34 v97.31,53.34 v95.57,53.34 v93.82,53.34 92.71,53.34 v92.08,53.34 v90.33,53.34 | v90.33,53.34 v87.95,53.34
  Bottom 0.406: v48.26,48.26 v59.69,48.26
  Bottom 0.813: v93.82,53.34 92.71,53.34 BATT.2
  Bottom 1.778: 87.95,57.15 v87.95,53.34 98.11,53.34
ADC1
  Top 0.406: IC1.39 ADC1.1
  Bottom 0.406: IC1.39 ADC1.1
ADC2
  Top 0.406: IC1.38 ADC2.1
  Bottom 0.406: IC1.38 ADC2.1
ADC3
  Top 0.406: IC1.37 ADC3.1
  Bottom 0.406: IC1.37 ADC3.1
ADC4
  Top 0.406: IC1.36 ADC4.1
  Bottom 0.406: IC1.36 ADC4.1
ADC5
  Top 0.406: IC1.35 ADC5.1
  Bottom 0.406: IC1.35 ADC5.1
ADC6
  Top 0.406: IC1.34 ADC6.1
  Bottom 0.406: IC1.34 ADC6.1
ADC7
  Top 0.406: IC1.33 ADC7.1
  Bottom 0.406: IC1.33 ADC7.1
ESC-BACK  (via drill 0.5)
  Top 0.406: ESC-BACK.1 31.75,35.34 31.75,41.3 32.99,42.55 v37.47,42.55
  Bottom 0.406: v37.47,42.55 66.99,42.55 68.58,40.96 IC1.18
ESC-FRONT
  Bottom 0.406: IC1.20 75.05,39.49 75.05,59.57 ESC-FRONT.1
ESC-LEFT  (via drill 0.5)
  Top 0.406: v59.69,50.8 72.87,50.8 73.66,51.59 IC1.21
  Bottom 0.406: ESC-LEFT.1 33.55,66.57 33.02,66.04 33.02,55.4 34.29,54.13 34.29,52.15 35.64,50.8 v59.69,50.8
ESC-RIGHT
  Bottom 0.406: 65.56,30 ESC-RIGHT.1 65.51,32.49 IC1.19
GND  (via drill 0.5, 1.1)
  Top 0.406: 85.72,77.47 84.38,78.82 84.3,78.82 84.3,78.9 | 85.65,77.55 88.9,80.8 | 48.26,55.4 46.99,57.63 46.83,57.47 C9.2 | 46.83,57.78 47.62,58.58 | 81.44,49.37 73.66,49.37 v73.66,49.85 | 79.38,47.15 83.26,47.15 v83.26,43.26
  Top 1.27: 0.64,55.88 LED3.K | 0.64,50.8 LED2.K | 0.64,45.72 LED1.K | LED-PWR.K 98.42,24.13
  Top 1.778: 90.81,61.75 v93.82,61.75 v95.57,61.75 v97.31,61.75 98.27,61.75
  Bottom 0.254: 62.87,10.95 62.87,12.06 | 51.28,36.99 51.91,37.62
  Bottom 0.406: Y1.2 53.98,31.27 56.04,31.27 | 84.3,78.9 85.64,77.55 MAG.1 | MAG.1 88.66,80.57 | MAG.1 85.57,77.47
  other vias: 33.5,41.12 53.98,16.83 52.86,13.97 38.42,21.91 66.2,20.32 64.61,28.1 58.42,24.92 60.96,24.13 55.88,24.61 63.02,19.21 62.23,22.23 81.28,38.81 81.28,31.19 71.12,46.83 55.88,46.83 45.72,46.83 30.16,44.13 18.89,51.59 59.85,89.69 55.88,44.13 55.88,40.64 46.51,41.43 90.73,24.37 88.82,33.26 53.02,22.7 48.9,23.02 74.93,63.5 72.39,59.69 66.04,16.19 63.5,16.19 63.5,14.29 63.66,80.8 63.66,71.91 72.23,82.71 42.07,87.15 45.09,67.31 52.71,73.66 54.77,65.72 17.78,58.42 24.29,56.04 22.23,58.74 26.67,66.67 74.93,35.56 49.85,25.24 50.01,31.43 32.39,11.43 21.43,54.77 74.93,29.92 1.43,77.31 7.14,80.8 4.29,70.01 15.08,76.36 13.81,68.1 2.38,87.15 69.69,76.04
  pour Top (isolate 0.305): 5.08,99.06 93.98,99.06 66.04,71.12 71.12,66.04 80.01,74.93 80.01,24.13 71.12,33.02 66.04,27.94 93.98,0 5.08,0 33.02,27.94 27.94,33.02 0,5.08 0,93.98 27.94,66.04 33.02,71.12
  pour Bottom (isolate 0.305): 5.08,99.06 93.98,99.06 66.04,71.12 71.12,66.04 80.01,74.93 80.01,24.13 71.12,33.02 66.04,27.94 93.98,0 5.08,0 33.02,27.94 27.94,33.02 0,5.08 0,93.98 27.94,66.04 33.02,71.12
  pour Bottom (isolate 0.635): 78.74,25.4 99.06,5.08 99.06,93.98 78.74,73.66
  pour Top (isolate 0.635): 78.74,25.4 99.06,5.08 99.06,93.98 78.74,73.66
MISO
  Top 0.406: IC1.7 SERVO4.1
  Bottom 0.406: BOOT.2 12.7,35.81 | 12.7,35.81 AVRISP.1 | 12.7,35.81 39.92,35.81 40.64,36.53 IC1.7
MOSI
  Top 0.406: IC1.6 SERVO3.1
  Bottom 0.406: AVRISP.4 16.83,42.23 33.97,42.23 IC1.6
N$1
  Bottom 0.406: Y1.3 52.07,30.8 52.07,36.83 IC1.12
N$2
  Bottom 0.406: Y1.1 55.88,35.88 IC1.13
N$3
  Top 0.406: LED3.A 4.45,53.34 R5.2
  Top 1.27: 0.64,53.34 LED3.A
N$4
  Top 0.406: LED2.A 4.45,48.26 R4.2
  Top 1.27: 0.64,48.26 LED2.A
N$5
  Top 0.406: LED1.A 4.45,43.18 R3.2
  Top 1.27: 0.64,43.18 LED1.A
N$6
  Top 0.813: X14.2 X15.2 X16.2 X17.2 SJ3.2
  Bottom 0.406: X14.2 74.93,96.2
  Bottom 0.813: 74.93,96.2 74.93,88.58
N$8  (via drill 0.5)
  Top 0.406: SJ15.1 45.24,60.58
  Top 0.813: RC1.2 RC2.2 RC3.2 RC4.2 RC5.2 RC6.2 SJ2.2 | 45.24,60.58 v46.77,59.05
  Bottom 0.813: v46.77,59.05 RC6.2 RC3.2 | RC2.2 RC1.2
N$11
  Top 0.406: IC1.40 20,58.74 R6.2 R7.1
N$12
  Top 0.406: SJ5.2 X18.2
N$13
  Top 0.406: D1.C R6.1
N$14
  Top 0.406: BATT-MON.2 12.38,61.07 D1.A 12.27,59.67 SJ16.1
N$15  (via drill 0.5)
  Top 0.406: v41.91,16.35 SJ6.2
  Bottom 0.406: SERIAL.2 v41.91,16.35
N$16
  Top 0.406: 90.73,43.18 C5.+ | 92.71,42.07 D2.C
  Top 0.813: 5V-REG.3 90.73,43.18 | C5.+ 90.65,43.02 90.81,43.02 90.81,42.07 92.71,42.07
N$17  (via drill 0.5)
  Bottom 0.406: BLUETOOTH.5 SJ7.2
  other vias: 61.59,15.24
N$18  (via drill 0.5)
  Bottom 0.406: BLUETOOTH.4 SJ8.2
  other vias: 59.05,15.24
N$19  (via drill 0.5)
  Bottom 0.406: FTDI.2 SJ9.2
  other vias: 69.85,15.24
N$20
  Top 0.813: SJ4.2 35.56,27.94 SERVO1.2 SERVO2.2 SERVO3.2 SERVO4.2
  Bottom 0.813: SERVO1.2 SERVO4.2
N$21  (via drill 0.5)
  Bottom 0.406: FTDI.3 SJ10.2
  other vias: 72.39,15.24
N$22
  Top 0.406: SJ12.2 26.67,2.06 25.88,1.27 22.46,1.27 XBEE.2
N$23
  Top 0.406: SJ11.2 26.67,4.6 25.88,3.81 22.75,3.81 XBEE.3
N$24
  Top 0.406: R12.2 93.34,21.59 LED-PWR.A
  Top 1.27: LED-PWR.A 98.42,21.59
N$25
  Top 0.406: C9.1 45.72,54.77 IC1.32
  Bottom 0.406: AREF-SEL.2 46.35,55.88 46.35,55.24 45.72,54.61 IC1.32
N$26
  Top 0.152: 96.93,98.45 96.93,98.91
N$27
  Top 0.152: 96.32,98.91 96.32,97.84
N$28
  Top 0.152: 96.62,98.91 96.62,98.15
N$29
  Top 0.152: 96.01,98.91 96.01,97.54
N$30
  Top 0.152: 95.4,98.91 95.4,96.93
N$31  (via drill 0.5)
  Top 0.406: v44.45,16.35 SJ13.2
  Bottom 0.406: SERIAL.3 v44.45,16.35
N$32  (via drill 0.5)
  Top 0.406: v46.99,16.35 SJ14.2
  Bottom 0.406: SERIAL.4 v46.99,16.35
N$33
  Top 0.152: 95.71,98.91 95.71,97.23
N$34
  Top 0.813: SJ15.2 ADC7.2 ADC6.2 ADC5.2 ADC4.2 ADC3.2 ADC2.2 ADC1.2 SJ17.2
  Bottom 0.813: ADC1.2 ADC3.2 | ADC4.2 ADC7.2
N$35
  Top 0.203: 96.93,95.3 98.75,95.3
N$36
  Top 0.152: 97.23,98.75 97.23,98.91
N$37
  Top 0.203: 97.33,95.71 98.75,95.71
N$38
  Top 0.203: 98.15,96.52 98.75,96.52
N$39
  Top 0.203: 97.74,96.11 98.75,96.11
N$40
  Top 0.203: 98.55,96.93 98.75,96.93
N$42
  Top 0.406: U$5.D- 8.62,75.41 D3.C 10.16,76.52 10.16,74.93 R14.1
N$43
  Top 0.406: U$5.D+ 8.26,74.61 9.21,73.66 R15.1 10.68,71.96 D4.C
RC-IN-1
  Top 0.406: IC1.24 RC1.1
  Bottom 0.406: IC1.24 RC1.1
RC-IN-2
  Top 0.406: IC1.25 RC2.1
  Bottom 0.406: IC1.25 RC2.1
RC-IN-3
  Top 0.406: IC1.26 RC3.1
  Bottom 0.406: IC1.26 RC3.1
RC-IN-4
  Top 0.406: IC1.27 RC4.1
  Bottom 0.406: IC1.27 RC4.1
RC-IN-5
  Top 0.406: IC1.28 RC5.1
  Bottom 0.406: IC1.28 RC5.1
RC-IN-6
  Top 0.406: IC1.29 RC6.1
  Bottom 0.406: IC1.29 RC6.1
RESET  (via drill 0.5)
  Top 0.406: v34.29,40.01 45.24,40.01 45.72,39.53 IC1.9 | RESET.2 3.88,35.88 R13.2 15.56,35.88 AVRISP.5
  Bottom 0.406: AVRISP.5 19.68,40.01 v34.29,40.01
RX0-HV
  Top 0.406: 57.15,22.86 57.15,36.83 IC1.14 | SJ10.1 71.37,12.7 60.01,12.7 59.05,13.65 SJ8.1 58.58,13.72 57.15,15.15 57.15,22.86 | IC4.4 56.23,22.86 57.15,22.86
RX0-LV
  Top 0.406: IC4.3 56.2,17.37 53.81,14.99 SJ14.1 44.86,12.86 38.51,12.86 SJ12.1
RX1-HV  (via drill 0.5)
  Top 0.406: IC5.4 v65.09,24.45 | SJ8.3 v59.05,16.67 | v72.39,16.83 SJ10.3
  Bottom 0.406: IC1.16 63.5,26.04 v65.09,24.45 65.09,15.24 | v59.05,16.67 61.59,16.67 63.02,15.24 65.09,15.24 | v72.39,16.83 70.17,16.83 68.58,15.24 65.25,15.24 65.09,15.24
RX1-LV  (via drill 0.5)
  Top 0.406: SJ12.3 v25.08,2.54 | v48.74,16.83 47.53,18.03 SJ14.3 | IC5.3 65.08,20.64 v66.04,21.59 | v67.31,14.29 v67.31,16.19 | v49.37,13.97 49.37,11.46 50.84,10 v65.72,10
  Bottom 0.406: v25.08,2.54 | v25.08,2.54 39.85,17.3 47.78,17.3 48.26,17.3 v48.74,16.83 49.37,16.19 v49.37,13.97 | v66.04,21.59 66.2,21.59 67.31,20.48 v67.31,16.19 | v67.31,14.29 65.72,12.7 v65.72,10
SCK
  Bottom 0.406: AVRISP.3 16.67,36.67 38.56,36.67 39.37,37.48 39.37,38.73 40.01,39.37 41.91,39.37 IC1.8
SCL  (via drill 0.5)
  Top 0.406: X17.4 X16.4 X15.4 X14.4 X18.4 48.26,86.23 GYRO.1 | IC1.22 R2.1 | v71.12,60.33 71.12,63.01 v72.63,64.53 MAG.4 | ACCEL.5 IMU.4
  Bottom 0.406: v71.12,60.33 IC1.22 | BARO.2 33.55,96.47 36.35,93.66 45.72,93.66 X18.4 | IMU.4 49.36,79.84 52.46,82.94 52.46,84.06 51.34,85.18 GYRO.1 | 67.31,69.85 67.31,75.88 69.85,78.42 X17.4 X14.4 | 67.31,69.85 | 67.31,69.85 v72.63,64.53
SDA  (via drill 0.5)
  Top 0.406: X14.3 X15.3 X16.3 X17.3 67.3,83.43 GYRO.2 48.32,83.43 46.99,84.76 46.99,95 X18.3 | IC1.23 R1.1 | MAG.3 80.18,73.99 v68.58,62.39
  Bottom 0.406: IC1.23 v68.58,62.39 63.34,67.63 50.16,67.63 | BARO.1 36.1,96.61 38.26,94.46 43.91,94.46 X18.3 | GYRO.2 47.47,79.75 IMU.3 47.47,72.39 50.16,69.69 50.16,67.63 | ACCEL.7 50.16,67.63 | ACCEL.7 | 72.39,88.58 X14.3 72.39,96.2
SERVO1
  Top 0.406: SERVO1.1 IC1.4
SERVO2
  Top 0.406: SERVO2.1 IC1.5
TX0-HV  (via drill 0.5)
  Top 0.406: IC1.15 R9.1 | SJ7.1 61.69,13.72 62.07,13.34 69.85,13.34 SJ9.1 70.39,13.72 71.12,14.45 71.12,17.68 70.55,18.26 v61.28,18.26 | v60.96,31.91 60.01,30.96 60.01,25.08 59.69,24.77 v59.69,19.53
  Bottom 0.406: v60.96,31.91 IC1.15 | v59.69,19.53 60.01,19.53 v61.28,18.26
TX0-LV  (via drill 0.5)
  Top 0.406: R9.2 v58.58,30.96 R8.2 | SJ11.1 28.19,5.33 36.67,13.81 43.27,13.81 SJ13.1 44.98,14.99 45.72,15.73 v45.72,20.32
  Bottom 0.406: v45.72,20.32 47.94,20.32 v58.58,30.96
TX1-HV  (via drill 0.5)
  Top 0.406: IC1.17 66.04,36.51 R10.1 64.45,35.24 63.5,34.29 63.5,32.7 60.96,30.16 v60.96,25.4 | SJ7.3 61.59,17.14 v64.14,17.14 69.85,17.14 SJ9.3
  Bottom 0.406: v64.14,17.14 64.14,24.24 62.98,25.4 v60.96,25.4
TX1-LV  (via drill 0.5)
  Top 0.406: R10.2 64.77,32.54 v62.23,30.01 R11.2 | SJ11.3 25.15,6.1 v38.26,19.21 | v44.45,19.21 SJ13.3
  Bottom 0.406: v38.26,19.21 v44.45,19.21 48.26,19.21 59.06,30.01 v62.23,30.01
USBD+
  Top 0.406: R15.2 12.7,68.89 11.11,67.31 8.98,67.31 7.62,65.94 R5.1 13.97,54.61 IC1.3
USBD-  (via drill 0.5)
  Top 0.406: R16.2 11.43,75.89 12.38,74.93 12.38,74.61 R14.2 14.66,74.3 15.56,73.4 15.56,66.99 14.61,66.04 9.76,66.04 8.41,64.69 8.41,62.23 9.21,61.44 v9.21,56.04 | R4.1 v9.21,49.53 16.51,49.53 IC1.2
  Bottom 0.406: v9.21,49.53 v9.21,56.04
USBPWR  (via drill 0.5)
  Top 0.406: 4.8,79.22 4.8,78.36 5.69,77.47 6.95,77.47 | 4.8,79.22 C10.+ 4.76,81.95 SJ18.1 | R16.1 9.47,78.74 9.47,78.69 8.26,77.47 6.95,77.47 | 6.95,77.47 U$5.VBUS | IC1.1 16.83,46.67 13.49,46.67 11.27,44.45 R3.1 v7.62,46.04 | v4.79,79.26 4.8,79.22
  Bottom 0.406: v4.79,79.26 3.17,77.63 3.17,63.66 7.62,59.21 v7.62,46.04

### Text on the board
_tsilk: G | V+ | D | C | C | D | V+ | G | 3V3 | 5V | 5V | 3V3 | V+ | GND | 2 | 3 | 4 | 5 | 6 | 6 | GND | SYS | 3V3 | V-RC | ESC | G | 5V | V+ | V+ | GND | G | 5V | 5V | 16 MHz | GND | 2 | 3 | 4 | ESC | SYS | GND | 3V3 | SER1 | 1 | 5V | SER1 | 3V3 | SER0 | SER0 | G | 0 | SER1 | SER0
_bsilk: 3V3 | 5V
